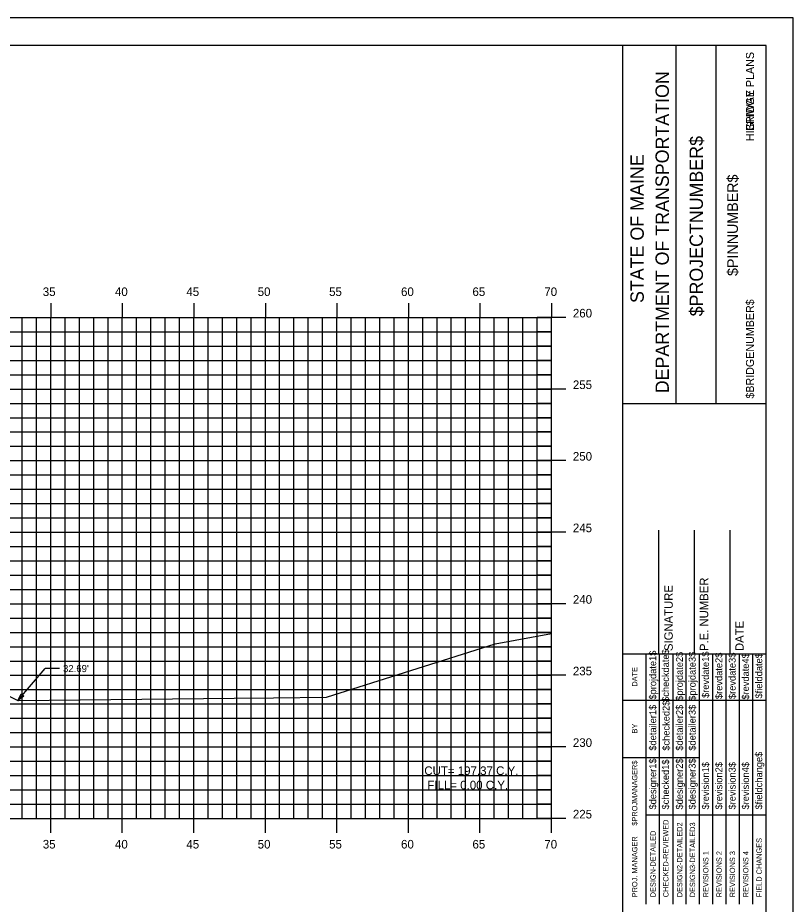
# Model space of a CAD drawing. Extents: x 1170543 to 1177585, y 609599 to 610623.
# Drawn here: x 1174281 to 1174335.2, y 609646.9 to 609708.8 of the extents above; entities that cross this region are included whole.
import ezdxf

# ---------------------------------------------------------------- set-up
doc = ezdxf.new("R2010")
doc.units = 0
for name, color, linetype in [('ANNOTATION', 7, 'Continuous'), ('BORDER', 7, 'Continuous'), ('BRIDGE_TITLE', 7, 'Continuous'), ('D_Roadway_Centerline', 7, 'Continuous'), ('D_Roadway_Centerline_Text', 7, 'Continuous'), ('D_Roadway_SlopeLines', 7, 'Continuous'), ('H_V ANNOTATION', 7, 'Continuous'), ('HIGHWAY_TITLE', 7, 'Continuous'), ('MAJOR', 7, 'Continuous'), ('MINOR', 7, 'Continuous'), ('PLOT BOUNDARY', 7, 'Continuous'), ('S_Roadway_Centerline', 7, 'Continuous')]:
    doc.layers.add(name, color=color, linetype=linetype)

msp = doc.modelspace()

# ---------------------------------------------------------------- linework, layer by layer
at = {"layer": 'ANNOTATION'}
for p in [(1174280.975, 609661.11), (1174283.891, 609663.344)]:
    msp.add_line(p, (1174282.891, 609663.344), dxfattribs=at)
msp.add_lwpolyline([(1174281.396, 609661.409), (1174280.975, 609661.11), (1174281.206, 609661.571)], close=True, dxfattribs=at)
at = {"layer": 'BORDER'}
for p, q in [((1174333.287, 609706.872), (1174173.287, 609706.872)), ((1174323.287, 609601.875), (1174323.287, 609706.875)), ((1174327.016, 609681.869), (1174327.016, 609706.869)), ((1174329.811, 609681.869), (1174329.811, 609706.869)), ((1174333.287, 609601.875), (1174333.287, 609706.875)), ((1174323.288, 609681.866), (1174333.287, 609681.866)), ((1174325.787, 609664.375), (1174325.787, 609673.023)), ((1174328.287, 609664.375), (1174328.287, 609673.023)), ((1174330.787, 609664.375), (1174330.787, 609673.023)), ((1174323.287, 609664.375), (1174333.287, 609664.375))]:
    msp.add_line(p, q, dxfattribs=at)
for points in [[(1174324.902, 609661.125), (1174324.902, 609664.375)], [(1174325.835, 609646.878), (1174325.835, 609664.375)], [(1174326.766, 609664.375), (1174326.766, 609646.878)], [(1174327.698, 609646.878), (1174327.698, 609664.375)], [(1174328.63, 609646.878), (1174328.63, 609664.375)], [(1174329.561, 609646.878), (1174329.561, 609664.375)], [(1174330.493, 609646.878), (1174330.493, 609664.375)], [(1174331.425, 609646.878), (1174331.425, 609664.375)], [(1174332.356, 609646.878), (1174332.356, 609664.375)], [(1174324.903, 609646.878), (1174324.903, 609663.669)], [(1174323.287, 609661.125), (1174333.287, 609661.125)], [(1174323.287, 609657.125), (1174324.903, 609657.125)], [(1174324.902, 609657.125), (1174328.629, 609657.125)], [(1174324.902, 609653.125), (1174333.287, 609653.125)]]:
    msp.add_lwpolyline(points, dxfattribs=at)
at = {"layer": 'D_Roadway_Centerline'}
msp.add_lwpolyline([(1174218.339, 609662.48), (1174224.426, 609665.524), (1174229.287, 609667.954), (1174232.287, 609668.014), (1174248.287, 609668.334), (1174264.287, 609668.014), (1174267.287, 609667.954), (1174272.148, 609665.524), (1174278.37, 609662.413), (1174280.975, 609661.11)], dxfattribs=at)
at = {"layer": 'D_Roadway_SlopeLines'}
msp.add_line((1174280.975, 609661.11), (1174280.975, 609661.11), dxfattribs=at)
at = {"layer": 'MAJOR'}
for p, q in [((1174283.287, 609688.874), (1174283.287, 609687.872)), ((1174288.287, 609688.874), (1174288.287, 609687.872)), ((1174293.287, 609688.874), (1174293.287, 609687.872)), ((1174298.287, 609688.874), (1174298.287, 609687.872)), ((1174303.287, 609688.874), (1174303.287, 609687.872)), ((1174308.287, 609688.874), (1174308.287, 609687.872)), ((1174313.287, 609688.874), (1174313.287, 609687.872)), ((1174318.287, 609688.874), (1174318.287, 609687.872)), ((1174178.287, 609687.872), (1174318.287, 609687.872)), ((1174178.287, 609687.872), (1174318.287, 609687.872)), ((1174283.287, 609652.872), (1174283.287, 609687.872)), ((1174288.287, 609652.872), (1174288.287, 609687.872)), ((1174293.287, 609652.872), (1174293.287, 609687.872)), ((1174298.287, 609652.872), (1174298.287, 609687.872)), ((1174303.287, 609652.872), (1174303.287, 609687.872)), ((1174308.287, 609652.872), (1174308.287, 609687.872)), ((1174313.287, 609652.872), (1174313.287, 609687.872)), ((1174319.289, 609687.872), (1174317.285, 609687.872)), ((1174318.287, 609652.872), (1174318.287, 609687.872)), ((1174318.287, 609652.872), (1174318.287, 609687.872)), ((1174178.287, 609682.872), (1174318.287, 609682.872)), ((1174319.289, 609682.872), (1174317.285, 609682.872)), ((1174178.287, 609677.872), (1174318.287, 609677.872)), ((1174319.289, 609677.872), (1174317.285, 609677.872)), ((1174178.287, 609672.872), (1174318.287, 609672.872)), ((1174319.289, 609672.872), (1174317.285, 609672.872)), ((1174178.287, 609667.872), (1174318.287, 609667.872)), ((1174319.289, 609667.872), (1174317.285, 609667.872)), ((1174178.287, 609662.872), (1174318.287, 609662.872)), ((1174319.289, 609662.872), (1174317.285, 609662.872)), ((1174178.287, 609657.872), (1174318.287, 609657.872)), ((1174319.289, 609657.872), (1174317.285, 609657.872)), ((1174178.287, 609652.872), (1174318.287, 609652.872)), ((1174178.287, 609652.872), (1174318.287, 609652.872)), ((1174283.287, 609651.87), (1174283.287, 609652.872)), ((1174288.287, 609651.87), (1174288.287, 609652.872)), ((1174293.287, 609651.87), (1174293.287, 609652.872)), ((1174298.287, 609651.87), (1174298.287, 609652.872)), ((1174303.287, 609651.87), (1174303.287, 609652.872)), ((1174308.287, 609651.87), (1174308.287, 609652.872)), ((1174313.287, 609651.87), (1174313.287, 609652.872)), ((1174319.289, 609652.872), (1174317.285, 609652.872)), ((1174318.287, 609651.87), (1174318.287, 609652.872))]:
    msp.add_line(p, q, dxfattribs=at)
at = {"layer": 'MINOR'}
for p, q in [((1174281.287, 609652.872), (1174281.287, 609687.872)), ((1174282.287, 609652.872), (1174282.287, 609687.872)), ((1174284.287, 609652.872), (1174284.287, 609687.872)), ((1174285.287, 609652.872), (1174285.287, 609687.872)), ((1174286.287, 609652.872), (1174286.287, 609687.872)), ((1174287.287, 609652.872), (1174287.287, 609687.872)), ((1174289.287, 609652.872), (1174289.287, 609687.872)), ((1174290.287, 609652.872), (1174290.287, 609687.872)), ((1174291.287, 609652.872), (1174291.287, 609687.872)), ((1174292.287, 609652.872), (1174292.287, 609687.872)), ((1174294.287, 609652.872), (1174294.287, 609687.872)), ((1174295.287, 609652.872), (1174295.287, 609687.872)), ((1174296.287, 609652.872), (1174296.287, 609687.872)), ((1174297.287, 609652.872), (1174297.287, 609687.872)), ((1174299.287, 609652.872), (1174299.287, 609687.872)), ((1174300.287, 609652.872), (1174300.287, 609687.872)), ((1174301.287, 609652.872), (1174301.287, 609687.872)), ((1174302.287, 609652.872), (1174302.287, 609687.872)), ((1174304.287, 609652.872), (1174304.287, 609687.872)), ((1174305.287, 609652.872), (1174305.287, 609687.872)), ((1174306.287, 609652.872), (1174306.287, 609687.872)), ((1174307.287, 609652.872), (1174307.287, 609687.872)), ((1174309.287, 609652.872), (1174309.287, 609687.872)), ((1174310.287, 609652.872), (1174310.287, 609687.872)), ((1174311.287, 609652.872), (1174311.287, 609687.872)), ((1174312.287, 609652.872), (1174312.287, 609687.872)), ((1174314.287, 609652.872), (1174314.287, 609687.872)), ((1174315.287, 609652.872), (1174315.287, 609687.872)), ((1174316.287, 609652.872), (1174316.287, 609687.872)), ((1174317.287, 609652.872), (1174317.287, 609687.872)), ((1174178.287, 609686.872), (1174318.287, 609686.872)), ((1174318.287, 609686.872), (1174317.285, 609686.872)), ((1174178.287, 609685.872), (1174318.287, 609685.872)), ((1174318.287, 609685.872), (1174317.285, 609685.872)), ((1174178.287, 609684.872), (1174318.287, 609684.872)), ((1174318.287, 609684.872), (1174317.285, 609684.872)), ((1174178.287, 609683.872), (1174318.287, 609683.872)), ((1174318.287, 609683.872), (1174317.285, 609683.872)), ((1174178.287, 609681.872), (1174318.287, 609681.872)), ((1174318.287, 609681.872), (1174317.285, 609681.872)), ((1174178.287, 609680.872), (1174318.287, 609680.872)), ((1174318.287, 609680.872), (1174317.285, 609680.872)), ((1174178.287, 609679.872), (1174318.287, 609679.872)), ((1174318.287, 609679.872), (1174317.285, 609679.872)), ((1174178.287, 609678.872), (1174318.287, 609678.872)), ((1174318.287, 609678.872), (1174317.285, 609678.872)), ((1174178.287, 609676.872), (1174318.287, 609676.872)), ((1174318.287, 609676.872), (1174317.285, 609676.872)), ((1174178.287, 609675.872), (1174318.287, 609675.872)), ((1174318.287, 609675.872), (1174317.285, 609675.872)), ((1174178.287, 609674.872), (1174318.287, 609674.872)), ((1174318.287, 609674.872), (1174317.285, 609674.872)), ((1174178.287, 609673.872), (1174318.287, 609673.872)), ((1174318.287, 609673.872), (1174317.285, 609673.872)), ((1174178.287, 609671.872), (1174318.287, 609671.872)), ((1174318.287, 609671.872), (1174317.285, 609671.872)), ((1174178.287, 609670.872), (1174318.287, 609670.872)), ((1174318.287, 609670.872), (1174317.285, 609670.872)), ((1174178.287, 609669.872), (1174318.287, 609669.872)), ((1174318.287, 609669.872), (1174317.285, 609669.872)), ((1174178.287, 609668.872), (1174318.287, 609668.872)), ((1174318.287, 609668.872), (1174317.285, 609668.872)), ((1174178.287, 609666.872), (1174318.287, 609666.872)), ((1174318.287, 609666.872), (1174317.285, 609666.872)), ((1174178.287, 609665.872), (1174318.287, 609665.872)), ((1174318.287, 609665.872), (1174317.285, 609665.872)), ((1174178.287, 609664.872), (1174318.287, 609664.872)), ((1174318.287, 609664.872), (1174317.285, 609664.872)), ((1174178.287, 609663.872), (1174318.287, 609663.872)), ((1174318.287, 609663.872), (1174317.285, 609663.872)), ((1174178.287, 609661.872), (1174318.287, 609661.872)), ((1174318.287, 609661.872), (1174317.285, 609661.872)), ((1174178.287, 609660.872), (1174318.287, 609660.872)), ((1174318.287, 609660.872), (1174317.285, 609660.872)), ((1174178.287, 609659.872), (1174318.287, 609659.872)), ((1174318.287, 609659.872), (1174317.285, 609659.872)), ((1174178.287, 609658.872), (1174318.287, 609658.872)), ((1174318.287, 609658.872), (1174317.285, 609658.872)), ((1174178.287, 609656.872), (1174318.287, 609656.872)), ((1174318.287, 609656.872), (1174317.285, 609656.872)), ((1174178.287, 609655.872), (1174318.287, 609655.872)), ((1174318.287, 609655.872), (1174317.285, 609655.872)), ((1174178.287, 609654.872), (1174318.287, 609654.872)), ((1174318.287, 609654.872), (1174317.285, 609654.872)), ((1174178.287, 609653.872), (1174318.287, 609653.872)), ((1174318.287, 609653.872), (1174317.285, 609653.872))]:
    msp.add_line(p, q, dxfattribs=at)
at = {"layer": 'PLOT BOUNDARY'}
msp.add_lwpolyline([(1174165.194, 609598.813), (1174335.194, 609598.813), (1174335.194, 609708.813), (1174165.194, 609708.813)], close=True, dxfattribs=at)
at = {"layer": 'S_Roadway_Centerline'}
msp.add_lwpolyline([(1174278.37, 609662.413), (1174280.975, 609661.111), (1174280.975, 609661.11), (1174280.975, 609661.11), (1174280.975, 609661.11), (1174280.976, 609661.11), (1174281.025, 609661.11), (1174281.028, 609661.11), (1174281.038, 609661.11), (1174296.115, 609661.269), (1174298.846, 609661.298), (1174302.56, 609661.337), (1174314.347, 609665.077), (1174318.287, 609665.786)], dxfattribs=at)

# ---------------------------------------------------------------- texts
at = {"layer": 'ANNOTATION'}
msp.add_text("32.69'", height=0.5, dxfattribs=at).set_placement((1174284.141, 609663.094))
at = {"layer": 'BORDER'}
for s, height, p in [('DEPARTMENT OF TRANSPORTATION', 0.93176, (1174326.494, 609682.578)), ('$PROJECTNUMBER$', 0.93176, (1174328.879, 609687.951)), ('STATE OF MAINE', 0.93176, (1174324.742, 609688.884)), ('$PINNUMBER$', 0.74527, (1174331.324, 609690.769)), ('P.E. NUMBER', 0.59055, (1174329.248, 609664.567)), ('SIGNATURE', 0.5906, (1174326.768, 609664.567)), ('DATE', 0.5906, (1174331.728, 609664.567)), ('$projdate1$', 0.48455, (1174325.61, 609661.176)), ('$checkdate$', 0.48455, (1174326.504, 609661.018)), ('$projdate2$', 0.48455, (1174327.473, 609661.097)), ('$projdate3$', 0.48455, (1174328.368, 609661.097)), ('$revdate1$', 0.4845, (1174329.299, 609661.294)), ('$revdate2$', 0.4845, (1174330.231, 609661.215)), ('$revdate3$', 0.4845, (1174331.163, 609661.215)), ('$revdate4$', 0.4845, (1174332.095, 609661.176)), ('$fielddate$', 0.48455, (1174333.026, 609661.254)), ('DATE', 0.3714, (1174324.291, 609662.081)), ('$detailer1$', 0.48455, (1174325.61, 609657.61)), ('$checked2$', 0.4845, (1174326.542, 609657.61)), ('$detailer2$', 0.48455, (1174327.473, 609657.61)), ('$detailer3$', 0.48455, (1174328.368, 609657.61)), ('BY', 0.3714, (1174324.291, 609658.81)), ('$fieldchange$', 0.48455, (1174333.026, 609653.498)), ('$PROJMANAGER$', 0.37275, (1174324.291, 609652.37)), ('$designer1$', 0.48455, (1174325.61, 609653.498)), ('$checked1$', 0.4845, (1174326.504, 609653.498)), ('$designer2$', 0.48455, (1174327.473, 609653.498)), ('$designer3$', 0.48455, (1174328.368, 609653.498)), ('$revision1$', 0.48455, (1174329.299, 609653.498)), ('$revision2$', 0.48455, (1174330.231, 609653.498)), ('$revision3$', 0.48455, (1174331.163, 609653.498)), ('$revision4$', 0.48455, (1174332.095, 609653.498)), ('CHECKED-REVIEWED', 0.37275, (1174326.468, 609647.363)), ('DESIGN-DETAILED', 0.37275, (1174325.574, 609647.363)), ('DESIGN2-DETAILED2', 0.37275, (1174327.437, 609647.363)), ('DESIGN3-DETAILED3', 0.37275, (1174328.331, 609647.363)), ('PROJ. MANAGER', 0.37275, (1174324.291, 609647.363)), ('FIELD CHANGES', 0.37275, (1174332.99, 609647.363)), ('REVISIONS 1', 0.37275, (1174329.263, 609647.363)), ('REVISIONS 2', 0.37275, (1174330.195, 609647.363)), ('REVISIONS 3', 0.37275, (1174331.126, 609647.363)), ('REVISIONS 4', 0.37275, (1174332.058, 609647.363))]:
    msp.add_text(s, height=height, rotation=90, dxfattribs=at).set_placement(p)
at = {"layer": 'BRIDGE_TITLE'}
for s, p in [('BRIDGE PLANS', (1174332.445, 609700.897)), ('$BRIDGENUMBER$', (1174332.445, 609682.203))]:
    msp.add_text(s, height=0.55901, rotation=90, dxfattribs=at).set_placement(p)
at = {"layer": 'D_Roadway_Centerline_Text'}
for s, p in [('CUT= 197.37 C.Y.', (1174309.399, 609655.908)), ('FILL= 0.00 C.Y.', (1174309.614, 609654.906))]:
    msp.add_text(s, height=0.6, dxfattribs=at).set_placement(p)
at = {"layer": 'H_V ANNOTATION'}
for s, p in [('35', (1174282.728, 609689.372)), ('40', (1174287.773, 609689.372)), ('45', (1174292.765, 609689.372)), ('50', (1174297.752, 609689.372)), ('55', (1174302.744, 609689.372)), ('60', (1174307.773, 609689.372)), ('65', (1174312.765, 609689.372)), ('70', (1174317.789, 609689.372)), ('260', (1174319.787, 609687.872)), ('255', (1174319.787, 609682.872)), ('250', (1174319.787, 609677.872)), ('245', (1174319.787, 609672.872)), ('240', (1174319.787, 609667.872)), ('235', (1174319.787, 609662.872)), ('230', (1174319.787, 609657.872)), ('225', (1174319.787, 609652.872)), ('35', (1174282.728, 609650.772)), ('40', (1174287.773, 609650.772)), ('45', (1174292.765, 609650.772)), ('50', (1174297.752, 609650.772)), ('55', (1174302.744, 609650.772)), ('60', (1174307.773, 609650.772)), ('65', (1174312.765, 609650.772)), ('70', (1174317.789, 609650.772))]:
    msp.add_text(s, height=0.6, dxfattribs=at).set_placement(p)
at = {"layer": 'HIGHWAY_TITLE'}
msp.add_text('HIGHWAY PLANS', height=0.55901, rotation=90, dxfattribs=at).set_placement((1174332.445, 609700.188))

doc.saveas('drawing.dxf')
